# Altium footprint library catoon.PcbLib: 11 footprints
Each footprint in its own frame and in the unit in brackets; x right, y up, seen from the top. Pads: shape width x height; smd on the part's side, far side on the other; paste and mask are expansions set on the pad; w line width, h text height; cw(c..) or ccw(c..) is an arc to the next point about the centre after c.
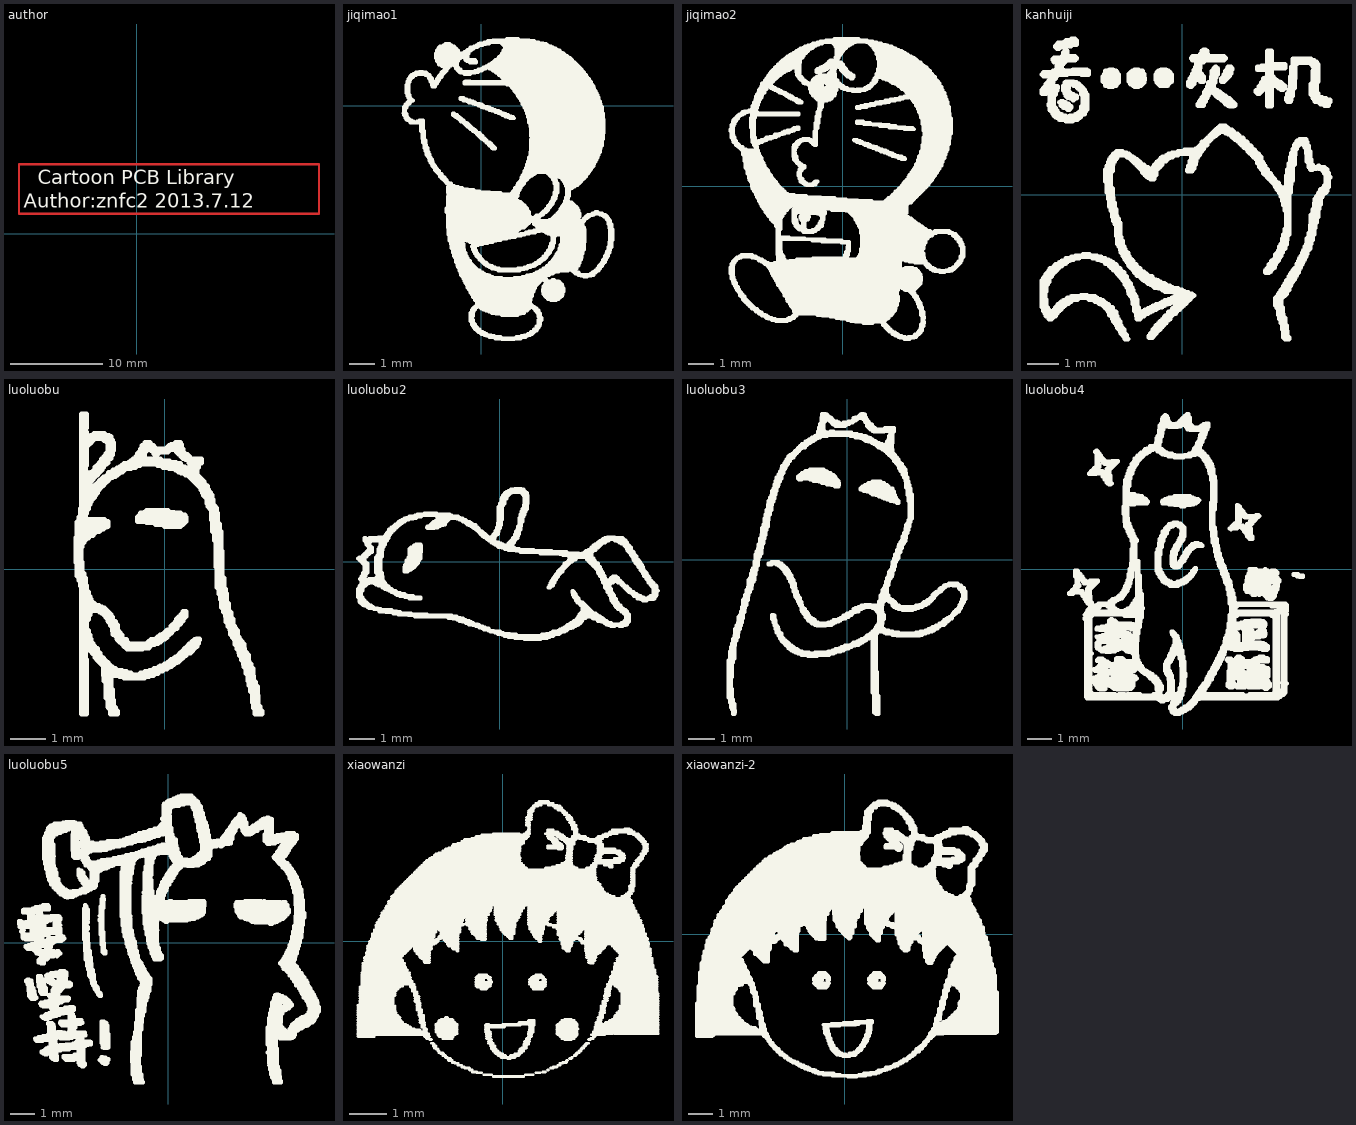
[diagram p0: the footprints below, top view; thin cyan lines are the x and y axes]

## author [mm]
Top Layer:
  lines w0.254: -12.7,2.159 19.685,2.159 19.685,7.493 -12.7,7.493 -12.7,2.159
Top Overlay:
  text "Author:znfc2 2013.7.12" at -12.192,2.794 h1.52
  text "Cartoon PCB Library" at -10.668,5.334 h1.52

## jiqimao1 [mm]
Top Overlay:
  drawing of 893 lines, arcs and shapes, not listed

## jiqimao2 [mm]
Top Overlay:
  drawing of 1083 lines, arcs and shapes, not listed

## kanhuiji [mm]
Top Overlay:
  drawing of 1022 lines, arcs and shapes, not listed

## luoluobu [mm]
Top Overlay:
  drawing of 576 lines, arcs and shapes, not listed

## luoluobu2 [mm]
Top Overlay:
  drawing of 573 lines, arcs and shapes, not listed

## luoluobu3 [mm]
Top Overlay:
  drawing of 804 lines, arcs and shapes, not listed

## luoluobu4 [mm]
Top Overlay:
  drawing of 1638 lines, arcs and shapes, not listed

## luoluobu5 [mm]
Top Overlay:
  drawing of 1518 lines, arcs and shapes, not listed

## xiaowanzi [mm]
Top Overlay:
  drawing of 683 lines, arcs and shapes, not listed

## xiaowanzi-2 [mm]
Top Overlay:
  drawing of 1007 lines, arcs and shapes, not listed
